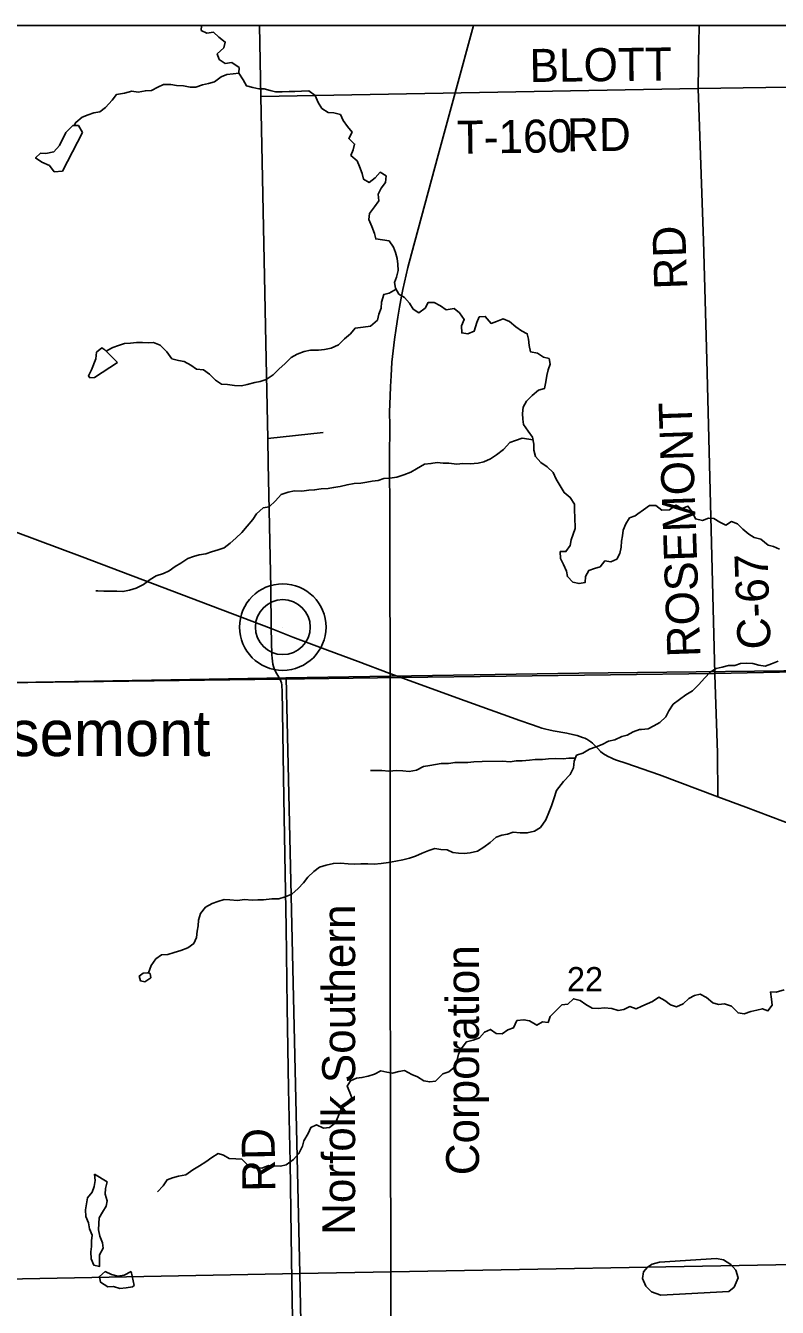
# Model space of a CAD drawing. Extents: x 0 to 34, y 0 to 22.
# Drawn here: x 7.577 to 8.87, y 17.72 to 19.924 of the extents above; entities that cross this region are included whole.
import ezdxf

# ---------------------------------------------------------------- set-up
doc = ezdxf.new("R2010")
doc.units = 0
for name, color, linetype in [('GM_X_Corporation', 7, 'Continuous'), ('GM_X_County_Road', 7, 'Continuous'), ('GM_X_County_Road_Text', 7, 'Continuous'), ('GM_X_Minor_Lake', 7, 'Continuous'), ('GM_X_Minor_River', 7, 'Continuous'), ('GM_X_Rail_Line', 7, 'Continuous'), ('GM_X_Rail_Line_Text', 7, 'Continuous'), ('GM_X_Section_Text', 7, 'Continuous'), ('GM_X_Township_Road', 7, 'Continuous'), ('GM_X_Township_Road_Text', 7, 'Continuous'), ('GM_X_Unincorporated', 7, 'Continuous'), ('GM_X_Unincorporated_Location', 7, 'Continuous'), ('GM_X_Unincorporated_Text', 7, 'Continuous'), ('SH_Data', 7, 'Continuous')]:
    doc.layers.add(name, color=color, linetype=linetype)

msp = doc.modelspace()

# ---------------------------------------------------------------- linework, layer by layer
at = {"layer": 'GM_X_Corporation'}
for points in [[(10.2438, 18.8341), (10.2438, 19.9239), (6.9951, 19.9239), (7.0002, 19.6505), (7.0062, 19.3415), (7.0072, 19.2641), (7.0169, 18.7868), (8.0146, 18.8), (8.2239, 18.8028), (8.7622, 18.8099), (9.5705, 18.8263)], [(8.025, 18.8024), (8.0487, 17.7782), (7.0352, 17.7584), (7.0317, 18.1483), (7.0159, 18.7847), (7.528, 18.794)], [(9.0322, 18.8161), (9.0559, 17.7965), (8.0487, 17.7782), (8.025, 18.8024), (8.5284, 18.8103)], [(8.0487, 17.7782), (9.0559, 17.7965), (9.0769, 16.778), (8.0702, 16.7576)], [(7.0352, 17.7584), (8.0487, 17.7782), (8.0702, 16.7576), (7.0559, 16.7358), (7.0543, 16.8256), (7.0404, 17.4662)]]:
    msp.add_lwpolyline(points, close=True, dxfattribs=at)
msp.add_lwpolyline([(10.2438, 13.7323), (10.2438, 18.8341), (9.5705, 18.8263), (8.7622, 18.8099), (8.2239, 18.8028), (8.0146, 18.8), (7.0169, 18.7868), (7.0182, 18.7109), (7.0206, 18.595), (7.0233, 18.4737), (7.0259, 18.3381), (7.0286, 18.1986), (7.0307, 18.0432), (7.0341, 17.8886), (7.0383, 17.6784), (7.0382, 17.6446), (7.0667, 16.1653), (7.068, 16.109), (7.0714, 16.0063)], dxfattribs=at)
at = {"layer": 'GM_X_County_Road'}
for points in [[(7.9995, 18.8873), (7.9987, 18.9563), (7.9944, 19.1707), (7.9936, 19.214), (7.9902, 19.3779), (7.9885, 19.4643), (7.9817, 19.8022), (7.9792, 19.9239)], [(8.7335, 19.8158), (8.7348, 19.8929), (8.7353, 19.9239)], [(9.5487, 19.825), (8.9278, 19.8189), (8.7335, 19.8158)], [(8.7625, 18.8074), (8.7624, 18.8094), (8.7484, 19.349), (8.743, 19.5541), (8.7335, 19.8158)], [(7.9995, 18.8873), (7.6742, 19.0102), (7.5204, 19.068), (7.3151, 19.1454), (7.1765, 19.1982), (7.0074, 19.2636)], [(8.0093, 18.8091), (8.0062, 18.8144), (8.0046, 18.8184), (8.0033, 18.8221), (8.0023, 18.8258), (8.0015, 18.8313), (8.0011, 18.8363), (8.0008, 18.8421), (7.9995, 18.8873)], [(8.2037, 18.8099), (8.1489, 18.8303), (8.1224, 18.8403), (8.0963, 18.8501), (8.0368, 18.8726), (7.9995, 18.8873)], [(8.0538, 16.9541), (8.0548, 16.9942), (8.0537, 17.036), (8.0508, 17.1483), (8.0465, 17.3105), (8.0381, 17.6035), (8.0351, 17.7658), (8.0336, 17.8439), (8.0318, 17.9693), (8.0295, 18.0958), (8.0272, 18.236), (8.0254, 18.3738), (8.0236, 18.4658), (8.0212, 18.5961), (8.0183, 18.7814), (8.018, 18.7867), (8.0177, 18.7905), (8.0171, 18.7937), (8.0162, 18.7965), (8.0148, 18.7995), (8.0093, 18.8091)], [(8.9219, 18.5399), (8.8156, 18.5798), (8.7674, 18.598), (8.6674, 18.6356), (8.6093, 18.6556), (8.5935, 18.6608), (8.5887, 18.6627), (8.5841, 18.6646), (8.5792, 18.6671), (8.5738, 18.67), (8.5691, 18.673), (8.566, 18.6759), (8.5613, 18.6809), (8.5565, 18.6856), (8.5522, 18.6898), (8.5493, 18.6924), (8.5458, 18.6949), (8.5423, 18.6969), (8.5387, 18.6986), (8.5348, 18.7), (8.5301, 18.7017), (8.5255, 18.703), (8.5201, 18.7044), (8.5078, 18.7071), (8.4845, 18.7113), (8.4771, 18.7129), (8.4715, 18.7143), (8.4651, 18.716), (8.4585, 18.7181), (8.447, 18.722), (8.427, 18.729), (8.333, 18.7629), (8.2241, 18.8022), (8.2037, 18.8099)], [(8.7674, 18.598), (8.7668, 18.6737), (8.7625, 18.8074)]]:
    msp.add_lwpolyline(points, dxfattribs=at)
at = {"layer": 'GM_X_Minor_Lake'}
for points in [[(7.6749, 19.74), (7.6679, 19.7521), (7.6584, 19.752), (7.6464, 19.7401), (7.6355, 19.718), (7.6254, 19.7069), (7.6121, 19.7041), (7.6029, 19.7048), (7.5943, 19.6964), (7.605, 19.6889), (7.618, 19.6833), (7.6264, 19.6727), (7.6405, 19.6736)], [(7.6405, 19.6736), (7.6749, 19.74)], [(7.7132, 19.3662), (7.7079, 19.3696), (7.6992, 19.3623), (7.6978, 19.3509), (7.6907, 19.3322), (7.6851, 19.3219), (7.6878, 19.3181), (7.6958, 19.3186), (7.7351, 19.3447)], [(7.7351, 19.3447), (7.7132, 19.3662)], [(7.7869, 18.2954), (7.7793, 18.2945), (7.7725, 18.2895), (7.7748, 18.2812), (7.7824, 18.2797), (7.7923, 18.2867), (7.7914, 18.2939)], [(7.7914, 18.2939), (7.7869, 18.2954)], [(7.6957, 17.9491), (7.6969, 17.9381), (7.6951, 17.9275), (7.6914, 17.9179), (7.6835, 17.908), (7.682, 17.8977), (7.6802, 17.8874), (7.6807, 17.876), (7.6854, 17.865), (7.687, 17.8548), (7.6913, 17.8442), (7.6906, 17.8343), (7.6903, 17.8248), (7.6893, 17.8153), (7.6897, 17.8031), (7.6944, 17.7925), (7.7043, 17.7903), (7.7041, 17.8101), (7.7105, 17.8215), (7.7096, 17.831), (7.705, 17.8424), (7.7022, 17.8534), (7.7029, 17.864), (7.7036, 17.8739), (7.7096, 17.8835), (7.7156, 17.8938), (7.7174, 17.9033), (7.7142, 17.9143), (7.7145, 17.9242), (7.7175, 17.9356)], [(7.7175, 17.9356), (7.6957, 17.9491)], [(8.667, 17.7975), (8.6545, 17.7943), (8.6466, 17.7893), (8.6399, 17.7808), (8.6378, 17.7694), (8.6437, 17.7562), (8.6537, 17.7468), (8.6697, 17.741), (8.7866, 17.7471), (8.7955, 17.7544), (8.8025, 17.7709), (8.7985, 17.7837), (8.7901, 17.7938), (8.7775, 17.8016), (8.7653, 17.8041)], [(8.7653, 17.8041), (8.667, 17.7975)], [(7.7588, 17.7813), (7.7467, 17.7751), (7.7356, 17.7735), (7.7246, 17.7764), (7.7139, 17.7813), (7.7041, 17.7732), (7.7061, 17.763), (7.7183, 17.7551), (7.7282, 17.7555), (7.7389, 17.7522), (7.7503, 17.7534), (7.7609, 17.755), (7.7639, 17.7577)], [(7.7639, 17.7577), (7.7588, 17.7813)]]:
    msp.add_lwpolyline(points, dxfattribs=at)
at = {"layer": 'GM_X_Minor_River'}
for points in [[(8.1723, 19.5782), (8.1676, 19.5907), (8.1687, 19.6006), (8.1769, 19.6121), (8.1848, 19.6228), (8.1836, 19.6338), (8.1888, 19.6445), (8.196, 19.6544), (8.197, 19.6655), (8.1871, 19.6718), (8.1784, 19.6623), (8.1682, 19.6542), (8.1583, 19.6598), (8.1559, 19.6697), (8.1512, 19.6814), (8.1473, 19.6913), (8.1366, 19.7007), (8.1407, 19.7102), (8.1429, 19.7201), (8.1329, 19.7296), (8.1385, 19.7406), (8.1308, 19.7505), (8.1235, 19.7607), (8.1185, 19.7713), (8.107, 19.7742), (8.0975, 19.7745), (8.0864, 19.7816), (8.0803, 19.7919), (8.0748, 19.8036), (8.0641, 19.8115), (8.0516, 19.811), (8.0401, 19.8105), (8.0303, 19.8105), (8.0181, 19.81), (8.0071, 19.8099), (7.9975, 19.8121), (7.9876, 19.8151), (7.9781, 19.8154), (7.9678, 19.8172), (7.9568, 19.8201), (7.951, 19.8304), (7.9436, 19.8421), (7.9443, 19.8516), (7.9317, 19.8602), (7.9203, 19.859), (7.91, 19.8658), (7.9068, 19.8752), (7.9178, 19.8856), (7.9203, 19.8955), (7.9096, 19.9042), (7.9, 19.9124), (7.8886, 19.9108), (7.8791, 19.9157), (7.8797, 19.9239)], [(7.9436, 19.8421), (7.9341, 19.8409), (7.9231, 19.8396), (7.9133, 19.8358), (7.9019, 19.8273), (7.8917, 19.8242), (7.8814, 19.8218), (7.8701, 19.8179), (7.8602, 19.8182), (7.8484, 19.8204), (7.8366, 19.8207), (7.8267, 19.8225), (7.8141, 19.8224), (7.8043, 19.8178), (7.7937, 19.8124), (7.783, 19.8119), (7.7709, 19.8095), (7.7598, 19.811), (7.7469, 19.8078), (7.7333, 19.8054), (7.7257, 19.7959), (7.7144, 19.7832), (7.7046, 19.7756), (7.6947, 19.774), (7.6849, 19.7705), (7.6743, 19.7662), (7.6633, 19.7574), (7.6606, 19.752)], [(8.6256, 19.0808), (8.6158, 19.0773), (8.6094, 19.0674), (8.6045, 19.0564), (8.6035, 19.0468), (8.6017, 19.0373), (8.6014, 19.0271), (8.5988, 19.0164), (8.5936, 19.0065), (8.5837, 19.0018), (8.5735, 19.0037), (8.5652, 18.9933), (8.5553, 18.9906), (8.5455, 18.9871), (8.5402, 18.9764), (8.5396, 18.9665), (8.5289, 18.9645), (8.5183, 18.9667), (8.509, 18.9765), (8.5074, 18.986), (8.502, 18.9974), (8.497, 19.0076), (8.4965, 19.0194), (8.5064, 19.0195), (8.5135, 19.0298), (8.5153, 19.0397), (8.519, 19.0496), (8.522, 19.0591), (8.5218, 19.0789), (8.5209, 19.0899), (8.5212, 19.1009), (8.5139, 19.1126), (8.5032, 19.1209), (8.4962, 19.1323), (8.4893, 19.144), (8.4842, 19.1554), (8.4739, 19.1652), (8.4631, 19.1727), (8.4539, 19.1832), (8.4511, 19.1939), (8.4514, 19.2041), (8.449, 19.2163), (8.4413, 19.2265), (8.4336, 19.2378), (8.432, 19.2473), (8.4316, 19.2572), (8.433, 19.2678), (8.4386, 19.2781), (8.448, 19.2877), (8.4593, 19.2969), (8.4696, 19.3001), (8.4718, 19.3115), (8.4736, 19.3221), (8.4758, 19.332), (8.4795, 19.3419), (8.4775, 19.3514), (8.468, 19.3536), (8.4572, 19.3604), (8.4454, 19.363), (8.4434, 19.374), (8.4422, 19.3846), (8.4398, 19.3941), (8.4299, 19.3993), (8.4203, 19.4057), (8.4092, 19.4151), (8.3985, 19.4196), (8.3871, 19.4153), (8.3777, 19.4118), (8.3677, 19.4239), (8.3574, 19.4231), (8.3529, 19.4132), (8.3485, 19.3983), (8.3379, 19.394), (8.3272, 19.3955), (8.3267, 19.4076), (8.3316, 19.4187), (8.3235, 19.43), (8.3139, 19.4372), (8.3006, 19.4352), (8.2907, 19.4423), (8.28, 19.4479), (8.2697, 19.4478), (8.2641, 19.4379), (8.2535, 19.4302), (8.2436, 19.4366), (8.2374, 19.4464), (8.2286, 19.4563), (8.219, 19.4623), (8.2132, 19.4725), (8.2116, 19.482), (8.2149, 19.4915), (8.2179, 19.5029), (8.2174, 19.5136), (8.2162, 19.5234), (8.213, 19.5337), (8.2099, 19.5432), (8.2022, 19.5541), (8.1911, 19.5556), (8.1793, 19.557), (8.1774, 19.5665), (8.1723, 19.5782)], [(8.2143, 19.4705), (8.2026, 19.464), (8.1931, 19.4617), (8.1891, 19.4483), (8.1884, 19.4381), (8.1843, 19.4278), (8.1821, 19.4175), (8.17, 19.4071), (8.1579, 19.4055), (8.1438, 19.4035), (8.1356, 19.3939), (8.1257, 19.3855), (8.1152, 19.3748), (8.1027, 19.369), (8.0913, 19.367), (8.081, 19.3661), (8.067, 19.3656), (8.056, 19.3633), (8.0442, 19.359), (8.0336, 19.3532), (8.0231, 19.3421), (8.0132, 19.334), (8.0027, 19.3233), (7.9906, 19.3152), (7.9807, 19.3121), (7.9712, 19.3101), (7.958, 19.3066), (7.9481, 19.3046), (7.9363, 19.3053), (7.9241, 19.3067), (7.9142, 19.3074), (7.9035, 19.3142), (7.8931, 19.3247), (7.8828, 19.3322), (7.871, 19.3333), (7.8614, 19.3401), (7.85, 19.3464), (7.8401, 19.3479), (7.8286, 19.3512), (7.8198, 19.3629), (7.8086, 19.3746), (7.7972, 19.3791), (7.7877, 19.3782), (7.7782, 19.3789), (7.7679, 19.3792), (7.7573, 19.378), (7.7474, 19.3772), (7.7371, 19.374), (7.7273, 19.3702), (7.7174, 19.3655), (7.7162, 19.3634)], [(8.4499, 19.2119), (8.4308, 19.2146), (8.4194, 19.2107), (8.4096, 19.2068), (8.3987, 19.195), (8.3869, 19.1861), (8.3764, 19.1792), (8.3654, 19.1738), (8.3555, 19.1718), (8.3418, 19.1706), (8.3293, 19.1712), (8.3186, 19.17), (8.3049, 19.1718), (8.295, 19.1717), (8.2851, 19.1728), (8.2741, 19.1708), (8.2631, 19.1699), (8.2495, 19.1615), (8.2396, 19.1561), (8.2275, 19.1514), (8.2158, 19.1475), (8.2036, 19.1455), (8.193, 19.1454), (8.1835, 19.1419), (8.1732, 19.1403), (8.1637, 19.1387), (8.1535, 19.1371), (8.1421, 19.1363), (8.1299, 19.1343), (8.1178, 19.1315), (8.1068, 19.1295), (8.0973, 19.1279), (8.0855, 19.1275), (8.0741, 19.1255), (8.0642, 19.125), (8.052, 19.1234), (8.0395, 19.1237), (8.0289, 19.1217), (8.0167, 19.1178), (8.0066, 19.1067), (7.996, 19.0963), (7.9857, 19.0947), (7.9744, 19.0844), (7.968, 19.0748), (7.9583, 19.063), (7.9489, 19.0523), (7.9387, 19.0427), (7.9289, 19.0339), (7.9187, 19.0262), (7.9084, 19.0227), (7.8967, 19.0188), (7.8872, 19.0157), (7.8754, 19.0137), (7.8659, 19.0113), (7.8561, 19.0078), (7.844, 18.9994), (7.8341, 18.9939), (7.8239, 18.9866), (7.8141, 18.9816), (7.8016, 18.9777), (7.7914, 18.9712), (7.7797, 18.9631), (7.7672, 18.9565), (7.7558, 18.953), (7.7444, 18.9507), (7.7337, 18.9513), (7.7117, 18.9512), (7.7014, 18.9518), (7.6976, 18.9518)], [(8.8735, 19.0239), (8.8636, 19.028), (8.854, 19.0305), (8.8418, 19.0406), (8.8303, 19.0435), (8.8208, 19.0495), (8.8108, 19.0581), (8.8012, 19.0671), (8.7913, 19.0712), (8.7815, 19.065), (8.7708, 19.0698), (8.7608, 19.0761), (8.7513, 19.0768), (8.7411, 19.0732), (8.729, 19.0757), (8.7235, 19.0878), (8.7161, 19.0976), (8.7063, 19.0937), (8.6952, 19.0992), (8.6843, 19.0915), (8.6714, 19.0906), (8.6611, 19.0988), (8.6501, 19.0987), (8.6399, 19.091), (8.6298, 19.0844), (8.6256, 19.0808)], [(8.8711, 18.8309), (8.8601, 18.8262), (8.8488, 18.8226), (8.8381, 18.8244), (8.8279, 18.8269), (8.8165, 18.8276), (8.8066, 18.8271), (8.7968, 18.8235), (8.7858, 18.8234), (8.7748, 18.8206), (8.765, 18.8186), (8.7544, 18.8124), (8.745, 18.8024), (8.7346, 18.7901), (8.7241, 18.7801), (8.7124, 18.7731), (8.7019, 18.765), (8.6906, 18.7569), (8.6835, 18.7458), (8.678, 18.7351), (8.6679, 18.7254), (8.6573, 18.7196), (8.6475, 18.7149), (8.6362, 18.7134)], [(7.7883, 18.2949), (7.7928, 18.3076), (7.8011, 18.319), (7.8109, 18.326), (7.8216, 18.3268), (7.8326, 18.3303), (7.844, 18.3334), (7.8561, 18.3381), (7.8663, 18.3454), (7.8711, 18.3557), (7.8722, 18.3667), (7.8736, 18.3762), (7.8747, 18.3858), (7.8776, 18.3972), (7.8866, 18.4083), (7.898, 18.4145), (7.9079, 18.418), (7.9185, 18.4211), (7.9284, 18.4208), (7.9417, 18.4197), (7.9535, 18.4214), (7.9668, 18.4199), (7.9767, 18.4204), (7.9862, 18.4209), (8.0006, 18.4221), (8.0124, 18.4226), (8.0234, 18.4257), (8.0348, 18.4304), (8.0461, 18.44), (8.0548, 18.4499), (8.0627, 18.4595), (8.0728, 18.4691), (8.0827, 18.4767), (8.094, 18.4803), (8.1066, 18.4834), (8.1187, 18.4835), (8.1321, 18.4828), (8.1423, 18.4818), (8.1537, 18.4826), (8.1655, 18.4823), (8.1766, 18.4821), (8.1887, 18.4829), (8.2013, 18.4849), (8.2138, 18.4873), (8.2256, 18.4897), (8.2373, 18.4924), (8.2476, 18.4959), (8.2589, 18.501), (8.2703, 18.5056), (8.2809, 18.5087), (8.2912, 18.5073), (8.3022, 18.5066), (8.3118, 18.5018), (8.3213, 18.5007), (8.3316, 18.5004), (8.3415, 18.5016), (8.354, 18.5044), (8.3649, 18.5113), (8.3763, 18.5194), (8.3861, 18.5282), (8.3959, 18.5321), (8.4058, 18.5337), (8.4157, 18.5368), (8.4279, 18.5357), (8.4397, 18.5358), (8.4522, 18.539), (8.4624, 18.5448), (8.4718, 18.5581), (8.477, 18.5711), (8.4814, 18.5825), (8.4855, 18.5944), (8.49, 18.6085), (8.502, 18.6241), (8.5137, 18.636), (8.5193, 18.6478), (8.5207, 18.6593), (8.5248, 18.6692), (8.5354, 18.6731), (8.5471, 18.6796), (8.5585, 18.6835), (8.5687, 18.6878), (8.5797, 18.6936), (8.5907, 18.6955), (8.6025, 18.7017), (8.6119, 18.7037), (8.6222, 18.7095), (8.6328, 18.7134), (8.6362, 18.7134)], [(8.5228, 18.6644), (8.5115, 18.6645), (8.5016, 18.6633), (8.4891, 18.6636), (8.4765, 18.6631), (8.4663, 18.6622), (8.4533, 18.6618), (8.4438, 18.6609), (8.4309, 18.6597), (8.421, 18.6596), (8.4104, 18.658), (8.3975, 18.659), (8.3621, 18.6588), (8.348, 18.6579), (8.3378, 18.6567), (8.3279, 18.657), (8.3157, 18.6569), (8.3043, 18.6549), (8.2918, 18.6548), (8.2823, 18.6536), (8.272, 18.6516), (8.2614, 18.65), (8.2496, 18.6434), (8.2367, 18.6414), (8.2257, 18.6425), (8.2154, 18.6431), (8.2017, 18.6419), (8.1899, 18.6429), (8.1797, 18.6432), (8.1701, 18.6432)], [(7.804, 17.9185), (7.8134, 17.9288), (7.8205, 17.9391), (7.83, 17.9426), (7.8402, 17.9457), (7.8528, 17.9477), (7.8645, 17.9566), (7.8762, 17.9635), (7.8872, 17.9704), (7.8974, 17.9777), (7.908, 17.9843), (7.9175, 17.9817), (7.9274, 17.9761), (7.9385, 17.9754), (7.9491, 17.9747), (7.9599, 17.9638), (7.9702, 17.9601), (7.9831, 17.9594), (7.9949, 17.9641), (8.0055, 17.9634), (8.0154, 17.9627), (8.0253, 17.9651), (8.0381, 17.9739), (8.0468, 17.9846), (8.0535, 17.9968), (8.0553, 18.0064), (8.0628, 18.0186), (8.0677, 18.0293), (8.0775, 18.0339), (8.0894, 18.0279), (8.0996, 18.0291), (8.1098, 18.0372), (8.1147, 18.0479), (8.1195, 18.0597), (8.1263, 18.0696), (8.138, 18.08), (8.1348, 18.0895), (8.1302, 18.1001), (8.1358, 18.1096), (8.146, 18.1139), (8.1555, 18.1151), (8.1662, 18.1175), (8.1772, 18.121), (8.1878, 18.1264), (8.1984, 18.1242), (8.2083, 18.1227), (8.219, 18.1255), (8.2288, 18.1271), (8.2411, 18.1203), (8.251, 18.1162), (8.2621, 18.1095), (8.272, 18.1077), (8.2822, 18.1089), (8.2947, 18.1212), (8.3049, 18.125), (8.3155, 18.1335), (8.3188, 18.1434), (8.3218, 18.1552), (8.3262, 18.1647), (8.3353, 18.1762), (8.3467, 18.1793), (8.3576, 18.1836), (8.3663, 18.1932), (8.3765, 18.1978), (8.3861, 18.1911), (8.3968, 18.1904), (8.4066, 18.1973), (8.4164, 18.2004), (8.422, 18.213), (8.4342, 18.2146), (8.4437, 18.2128), (8.4563, 18.2049), (8.4662, 18.2107), (8.4757, 18.21), (8.479, 18.2199), (8.4885, 18.2295), (8.4994, 18.2399), (8.5096, 18.2411), (8.5194, 18.2507), (8.5309, 18.2473), (8.5408, 18.2406), (8.5512, 18.2346), (8.5626, 18.2339), (8.5721, 18.2351), (8.5854, 18.2337), (8.5961, 18.2304), (8.606, 18.232), (8.6162, 18.237), (8.6269, 18.2333), (8.6371, 18.2379)], [(8.8815, 18.2657), (8.8678, 18.2621), (8.8583, 18.2624), (8.8596, 18.2498), (8.8609, 18.2396), (8.8538, 18.2296), (8.8443, 18.2333), (8.8345, 18.2309), (8.8246, 18.2289), (8.8129, 18.2249), (8.8023, 18.2263), (8.7911, 18.2376), (8.7793, 18.242), (8.769, 18.2404), (8.7588, 18.2437), (8.748, 18.253), (8.7373, 18.2582), (8.7275, 18.2562), (8.7177, 18.2508), (8.7079, 18.2419), (8.6966, 18.2364), (8.6863, 18.2401), (8.6767, 18.2476), (8.6664, 18.2532), (8.6555, 18.2458), (8.6371, 18.2379)]]:
    msp.add_lwpolyline(points, dxfattribs=at)
at = {"layer": 'GM_X_Rail_Line'}
msp.add_lwpolyline([(8.2054, 17.5732), (8.205, 17.7287), (8.2044, 18.088), (8.2043, 18.3038), (8.2043, 18.4138), (8.2043, 18.5018), (8.2039, 18.8088), (8.2034, 19.0039), (8.2034, 19.0764), (8.2031, 19.1805), (8.2034, 19.2357), (8.2029, 19.2595), (8.2039, 19.2869), (8.2046, 19.3033), (8.2055, 19.3214), (8.2072, 19.345), (8.2091, 19.3647), (8.2113, 19.3839), (8.2142, 19.4036), (8.217, 19.4224), (8.2199, 19.4395), (8.2234, 19.4586), (8.2258, 19.4702), (8.2345, 19.508), (8.2405, 19.5316), (8.2867, 19.7012), (8.3161, 19.8083), (8.3476, 19.9239)], dxfattribs=at)
at = {"layer": 'GM_X_Township_Road'}
for p, q in [((8.7335, 19.8158), (7.9817, 19.8022)), ((7.9936, 19.214), (8.0888, 19.2245))]:
    msp.add_line(p, q, dxfattribs=at)
at = {"layer": 'GM_X_Unincorporated'}
for radius in [0.0744, 0.0472]:
    msp.add_circle((8.0194, 18.8896), radius, dxfattribs=at)
at = {"layer": 'GM_X_Unincorporated_Location'}
msp.add_line((8.0194, 18.8896), (8.0194, 18.8896), dxfattribs=at)
at = {"layer": 'SH_Data'}
msp.add_line((3.4438, 19.9239), (10.2438, 19.9239), dxfattribs=at)

# ---------------------------------------------------------------- texts
at = {"layer": 'GM_X_County_Road_Text'}
for s, rotation, p in [('RD', 91.9758, (8.7152, 19.4712)), ('ROSEMONT', 92.0006, (8.7377, 18.8387)), ('C-67', 92.0565, (8.8587, 18.8522)), ('RD', 90.9872, (8.0069, 17.9191))]:
    msp.add_text(s, height=0.05682, rotation=rotation, dxfattribs=at).set_placement(p)
at = {"layer": 'GM_X_Rail_Line_Text'}
for s, p in [('Norfolk Southern', (8.1438, 17.8445)), ('Corporation', (8.3569, 17.947))]:
    msp.add_text(s, height=0.056629, rotation=90, dxfattribs=at).set_placement(p)
at = {"layer": 'GM_X_Section_Text'}
msp.add_text('22', height=0.04186, rotation=0, dxfattribs=at).set_placement((8.508, 18.2632))
at = {"layer": 'GM_X_Township_Road_Text'}
for s, rotation, p in [('BLOTT', 0.641, (8.444, 19.8269)), ('T-160', 0.8421, (8.319, 19.7034)), ('RD', 0.4937, (8.5084, 19.7077))]:
    msp.add_text(s, height=0.05682, rotation=rotation, dxfattribs=at).set_placement(p)
at = {"layer": 'GM_X_Unincorporated_Text'}
msp.add_text('Rosemont', height=0.07898, rotation=0, dxfattribs=at).set_placement((7.4134, 18.6678))

doc.saveas('drawing.dxf')
